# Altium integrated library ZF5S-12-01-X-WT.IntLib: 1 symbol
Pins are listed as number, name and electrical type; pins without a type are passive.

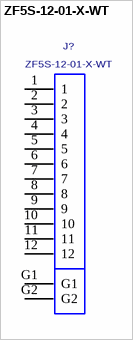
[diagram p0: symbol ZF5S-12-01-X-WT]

## ZF5S-12-01-X-WT
designator J?
ZERO INSERTION FORCE 0.5MM ASSEMBLY, 01 LEAD STYLE.; MANUFACTURER: SAMTEC
footprint ZF5S-12-01-X-WT
pins: 1, 2, 3, 4, 5, 6, 7, 8, 9, 10, 11, 12, G1, G2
